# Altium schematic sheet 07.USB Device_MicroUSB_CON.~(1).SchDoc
size A4; CheckedBy: 20170717; Author: 赵金生; CompanyName: 广州周立功单片机科技有限公司; DocumentNumber: 6; SheetNumber: 6; SheetTotal: 7; PageSetup: Record=PageOptions¦CenterHorizontal=True¦CenterVertical=True¦PrintScale=1.00¦XCorrection=1.00¦YCorrection=1.00¦PrintKind=0¦BorderSize=5000000¦LeftOffset=0¦BottomOffset=0¦Orientation=2¦PaperLength=1000¦PaperWidth=1000¦Scale=100¦PaperSource=7¦PrintQuality=600¦MediaType=1¦DitherType=10¦PaperKind=A4¦PrintScaleMode=1; DesignDate: 20170717; CheckDate: 赵金生; SheetName: USB接口电路; SheetVersion: <图纸版本>; SheetDescription: USB接口电路，纯供电，没有usb信号
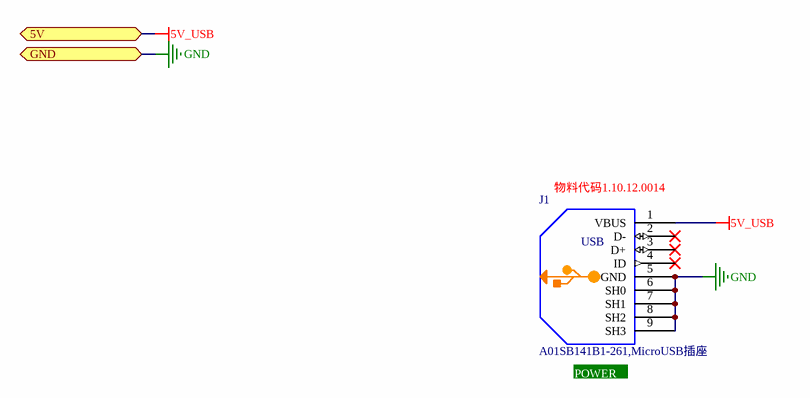
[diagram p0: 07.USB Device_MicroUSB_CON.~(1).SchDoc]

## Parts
J1  A01SB141B1-261,MicroUSB插座  [MICROUSB-5S]

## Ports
5V, GND

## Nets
5V_USB: J1.1(VBUS) ; port 5V
GND: J1.5(GND) J1.6(SH0) J1.7(SH1) J1.8(SH2) J1.9(SH3) ; port GND

Not connected (* = marked no-connect by the designer): J1 2(D-)* 3(D+)* 4(ID)*

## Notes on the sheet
- (near J1) 物料代码1.10.12.0014
- (near J1) POWER

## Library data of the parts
J1 = 1.10.12.0014: A01SB141B1-261,MicroUSB插座,SMT,艾立信,RoHS; PCB备注: 141030lmd; 器件优选方案: 正常状态，可以选用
